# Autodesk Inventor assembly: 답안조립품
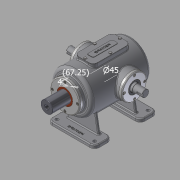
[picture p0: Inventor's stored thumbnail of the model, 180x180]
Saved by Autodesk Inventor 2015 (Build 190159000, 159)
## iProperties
Created: 2016-02
Part Number: 답안조립품
Document SubType Name: Assembly
Designer: Administrator
Author: Administrator
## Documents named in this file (15)
- C:\Users\Administrator\Desktop\360220V1003\답안조립품.iam
- C:\Users\Administrator\Desktop\360220V1003\본체.ipt
- C:\Users\Administrator\Desktop\360220V1003\베어링 6205.ipt
- 베어링 6205.ipt
- C:\Users\Administrator\Desktop\360220V1003\축 커버.ipt
- C:\Users\Administrator\Desktop\360220V1003\오일실.ipt
- 오일실.ipt
- C:\Users\Administrator\Desktop\360220V1003\볼트 M4x0.7.ipt
- C:\Users\Administrator\Desktop\360220V1003\편심축.ipt
- C:\Users\Administrator\Desktop\360220V1003\상부커버.ipt
- C:\Users\Administrator\Desktop\360220V1003\육각머리볼트 M4.ipt
- C:\Users\Administrator\Desktop\360220V1003\슬라이드 커버.ipt
- C:\Users\Administrator\Desktop\360220V1003\부시.ipt
- C:\Users\Administrator\Desktop\360220V1003\가변스프링.ipt
- C:\Users\Administrator\Desktop\360220V1003\슬라이드.ipt
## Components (13 placed, 2 different names)
1. 가변스프링:1
2. M4x0.7:1
3. M4x0.7:3
4. M4x0.7:4
5. M4x0.7:5
6. M4x0.7:2
7. M4x0.7:6
8. M4x0.7:7
9. M4x0.7:8
10. M4x0.7:9
11. M4x0.7:10
12. M4x0.7:11
13. M4x0.7:12
